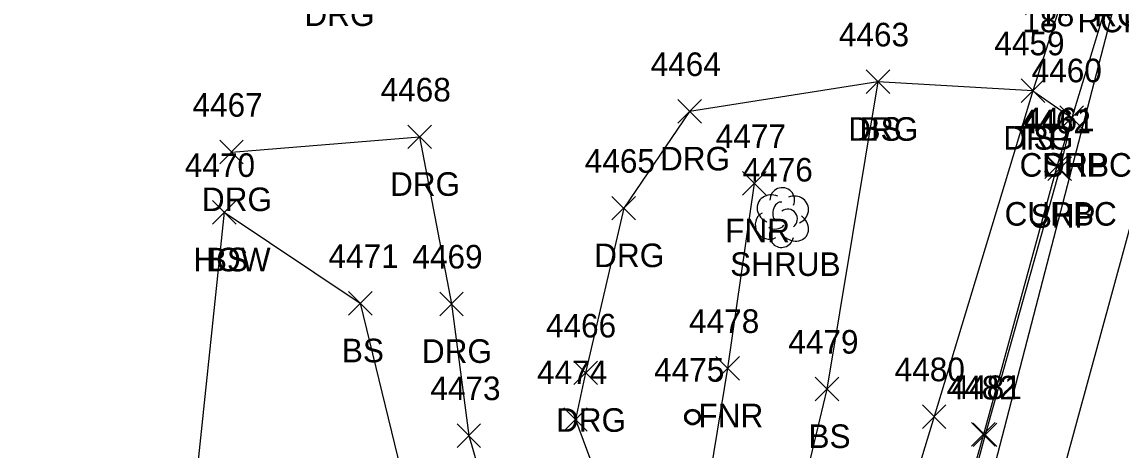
# Model space of a CAD drawing. Extents: x 1443912 to 1445411, y 621446 to 623693.
# Drawn here: x 1444817.3 to 1444910.4, y 623202.8 to 623239.1 of the extents above; entities that cross this region are included whole.
import ezdxf

# ---------------------------------------------------------------- set-up
doc = ezdxf.new("R2010")
doc.units = 0
for name, color, linetype in [('D_C', 7, 'Continuous'), ('DCP', 7, 'Continuous'), ('L_A', 7, 'Continuous'), ('L_I', 7, 'Continuous'), ('L_TIC', 7, 'Continuous'), ('LBC', 7, 'Continuous'), ('LELB', 7, 'Continuous'), ('LFNC', 7, 'Continuous'), ('LSH', 7, 'Continuous'), ('P_A', 7, 'Continuous'), ('P_I', 7, 'Continuous'), ('P_TIC', 7, 'Continuous'), ('PET', 7, 'Continuous'), ('PSP', 7, 'Continuous'), ('R_A', 7, 'Continuous'), ('R_I', 7, 'Continuous'), ('R_TIC', 7, 'Continuous'), ('RC', 7, 'Continuous'), ('RDG', 7, 'Continuous'), ('RDP', 7, 'Continuous'), ('U_I', 7, 'Continuous'), ('UWW', 7, 'Continuous')]:
    doc.layers.add(name, color=color, linetype=linetype)

msp = doc.modelspace()

# ---------------------------------------------------------------- linework, layer by layer
at = {"layer": 'DCP'}
msp.add_lwpolyline([(1444911.563, 623247.238), (1444894.245, 623180.504)], dxfattribs=at)
at = {"layer": 'L_TIC'}
for points in [[(1444888.818, 623233.04), (1444890.818, 623235.04)], [(1444890.818, 623233.04), (1444888.818, 623235.04)], [(1444901.957, 623232.286), (1444903.957, 623234.286)], [(1444903.957, 623232.286), (1444901.957, 623234.286)], [(1444878.337, 623224.428), (1444880.337, 623226.428)], [(1444880.337, 623224.428), (1444878.337, 623226.428)], [(1444833.425, 623221.976), (1444835.425, 623223.976)], [(1444835.425, 623221.976), (1444833.425, 623223.976)], [(1444833.425, 623221.976), (1444835.425, 623223.976)], [(1444835.425, 623221.976), (1444833.425, 623223.976)], [(1444844.947, 623214.264), (1444846.947, 623216.264)], [(1444846.947, 623214.264), (1444844.947, 623216.264)], [(1444876.076, 623208.754), (1444878.076, 623210.754)], [(1444878.076, 623208.754), (1444876.076, 623210.754)], [(1444884.494, 623207), (1444886.494, 623209)], [(1444886.494, 623207), (1444884.494, 623209)], [(1444893.586, 623204.659), (1444895.586, 623206.659)], [(1444895.586, 623204.659), (1444893.586, 623206.659)]]:
    msp.add_lwpolyline(points, dxfattribs=at)
at = {"layer": 'LBC'}
msp.add_lwpolyline([(1444834.425, 623222.976), (1444831.618, 623196.323)], dxfattribs=at)
at = {"layer": 'LELB'}
for points in [[(1444902.957, 623233.286), (1444894.586, 623205.659), (1444889.191, 623187.939), (1444879.578, 623174.577), (1444872.118, 623162.043), (1444873.893, 623154.396), (1444865.845, 623150.18), (1444852.3, 623142.76)], [(1444889.818, 623234.04), (1444885.494, 623208), (1444880.825, 623188.505), (1444872.453, 623183.102), (1444862.516, 623178.532), (1444852.576, 623179.818)], [(1444834.425, 623222.976), (1444845.947, 623215.264), (1444850.417, 623196.823), (1444852.576, 623179.818), (1444839.694, 623178.175), (1444838.752, 623160.519), (1444860.598, 623157.594), (1444858.828, 623151.991), (1444849.747, 623147.245), (1444824.976, 623155.314)]]:
    msp.add_lwpolyline(points, dxfattribs=at)
at = {"layer": 'LFNC'}
msp.add_lwpolyline([(1444879.337, 623225.428), (1444877.076, 623209.754), (1444874.413, 623193.583)], dxfattribs=at)
at = {"layer": 'LSH'}
msp.add_line((1444881.665, 623222.586), (1444881.665, 623222.586), dxfattribs=at)
msp.add_line((1444881.665, 623222.586), (1444881.665, 623222.586), dxfattribs=at)
msp.add_arc((1444881.712, 623224.02), 1.047, 335.52715, 180.95627, dxfattribs=at)
for centre, major_axis, ratio, start_param, end_param in [((1444880.873, 623223.253), (1.21, -0.512), 0.895232, 1.570796, 4.712389), ((1444882.707, 623223.169), (-1.141, -0.483), 0.949671, 1.570796, 4.712389), ((1444881.457, 623223.044), (-0.208, -0.792), 0.645439, 3.141593, 6.283185), ((1444882.165, 623222.419), (-0.5, 0.667), 0.989748, 3.141593, 6.283185), ((1444880.582, 623221.877), (0.584, -1.042), 0.959034, 3.141593, 6.283185), ((1444882.665, 623221.753), (-1.09, 0.792), 0.841452, 1.570796, 4.712389), ((1444881.665, 623221.086), (0.265, 1.061), 0.942809, 1.570796, 4.712389), ((1444881.207, 623221.836), (-0.625, -0.083), 0.423636, 0, 3.141593)]:
    msp.add_ellipse(centre, major_axis=major_axis, ratio=ratio, start_param=start_param, end_param=end_param, dxfattribs=at)
at = {"layer": 'P_TIC'}
for points in [[(1444905.243, 623229.997), (1444907.243, 623231.997)], [(1444907.243, 623229.997), (1444905.243, 623231.997)], [(1444904.229, 623225.669), (1444906.229, 623227.669)], [(1444906.229, 623225.669), (1444904.229, 623227.669)], [(1444897.903, 623203.12), (1444899.903, 623205.12)], [(1444899.903, 623203.12), (1444897.903, 623205.12)]]:
    msp.add_lwpolyline(points, dxfattribs=at)
at = {"layer": 'PET'}
msp.add_lwpolyline([(1445036.702, 623677.704), (1445026.384, 623639.781), (1445008.648, 623576.155), (1444996.948, 623532.888), (1444979.777, 623472.466), (1444964.829, 623416.219), (1444955.709, 623382.545), (1444949.165, 623358.134), (1444939.286, 623323.432), (1444926.274, 623275.909), (1444914.827, 623235.039), (1444901.528, 623186.461), (1444892.14, 623152.692), (1444883.143, 623119.129), (1444870.129, 623073.226), (1444861.494, 623043.31), (1444850.844, 623006.823), (1444834.615, 622954.828), (1444817.277, 622898.327)], dxfattribs=at)
at = {"layer": 'PSP'}
msp.add_lwpolyline([(1444938.45, 623347.365), (1444929.025, 623313.433), (1444928.238, 623309.81), (1444922.874, 623290.92), (1444911.871, 623250.743), (1444910.828, 623246.919), (1444910.341, 623244.449), (1444906.243, 623230.997), (1444905.229, 623226.669), (1444898.903, 623204.12), (1444894.62, 623188.308), (1444891.502, 623176.899), (1444890.541, 623173.344), (1444886.055, 623157.557), (1444885.108, 623153.679), (1444881.771, 623141.713), (1444880.574, 623137.991), (1444874.863, 623117.344), (1444874.119, 623114.36), (1444864.329, 623079.142), (1444854.722, 623044.471)], dxfattribs=at)
at = {"layer": 'R_TIC'}
for points in [[(1444888.818, 623233.04), (1444890.818, 623235.04)], [(1444890.818, 623233.04), (1444888.818, 623235.04)], [(1444901.957, 623232.286), (1444903.957, 623234.286)], [(1444903.957, 623232.286), (1444901.957, 623234.286)], [(1444901.957, 623232.286), (1444903.957, 623234.286)], [(1444903.957, 623232.286), (1444901.957, 623234.286)], [(1444872.863, 623230.527), (1444874.863, 623232.527)], [(1444874.863, 623230.527), (1444872.863, 623232.527)], [(1444905.243, 623229.997), (1444907.243, 623231.997)], [(1444907.243, 623229.997), (1444905.243, 623231.997)], [(1444905.243, 623229.997), (1444907.243, 623231.997)], [(1444907.243, 623229.997), (1444905.243, 623231.997)], [(1444849.979, 623228.373), (1444851.979, 623230.373)], [(1444851.979, 623228.373), (1444849.979, 623230.373)], [(1444834.037, 623227.079), (1444836.037, 623229.079)], [(1444836.037, 623227.079), (1444834.037, 623229.079)], [(1444903.972, 623225.847), (1444905.972, 623227.847)], [(1444905.972, 623225.847), (1444903.972, 623227.847)], [(1444867.282, 623222.33), (1444869.282, 623224.33)], [(1444869.282, 623222.33), (1444867.282, 623224.33)], [(1444852.681, 623214.214), (1444854.681, 623216.214)], [(1444854.681, 623214.214), (1444852.681, 623216.214)], [(1444864.047, 623208.372), (1444866.047, 623210.372)], [(1444866.047, 623208.372), (1444864.047, 623210.372)], [(1444863.189, 623204.416), (1444865.189, 623206.416)], [(1444865.189, 623204.416), (1444863.189, 623206.416)], [(1444854.147, 623203.057), (1444856.147, 623205.057)], [(1444856.147, 623203.057), (1444854.147, 623205.057)], [(1444897.756, 623203.149), (1444899.756, 623205.149)], [(1444899.756, 623203.149), (1444897.756, 623205.149)]]:
    msp.add_lwpolyline(points, dxfattribs=at)
at = {"layer": 'RC'}
msp.add_lwpolyline([(1444906.243, 623230.997), (1444904.972, 623226.847), (1444898.756, 623204.149), (1444894.271, 623188.271), (1444891.321, 623176.989), (1444890.541, 623173.344)], dxfattribs=at)
at = {"layer": 'RDG'}
for points in [[(1444902.957, 623233.286), (1444889.818, 623234.04), (1444873.863, 623231.527), (1444868.282, 623223.33), (1444865.047, 623209.372), (1444864.189, 623205.416), (1444872.453, 623183.102), (1444879.578, 623174.577), (1444885.885, 623171.627)], [(1444835.037, 623228.079), (1444850.979, 623229.373), (1444853.681, 623215.214), (1444855.147, 623204.057), (1444862.516, 623178.532), (1444867.375, 623173.1)]]:
    msp.add_lwpolyline(points, dxfattribs=at)
at = {"layer": 'RDP'}
msp.add_lwpolyline([(1444910.341, 623244.449), (1444906.44, 623244.251), (1444902.957, 623233.286), (1444906.243, 623230.997)], dxfattribs=at)
at = {"layer": 'UWW'}
for radius in [0.667, 0.625, 0.583, 0.542]:
    msp.add_circle((1444874.112, 623205.622), radius, dxfattribs=at)

# ---------------------------------------------------------------- texts
at = {"layer": 'D_C'}
for p in [(1444903.487, 623238.747), (1444902.06, 623238.238)]:
    msp.add_text('18" RCP GOOD', height=2, dxfattribs=at).set_placement(p)
at = {"layer": 'L_A'}
for s, p in [('BS', (1444888.259, 623229.04)), ('TS', (1444901.367, 623228.286)), ('FNR', (1444876.873, 623220.428)), ('HOW', (1444831.811, 623217.976)), ('BS', (1444832.866, 623217.976)), ('SHRUB', (1444877.295, 623217.586)), ('BS', (1444844.388, 623210.264)), ('FNR', (1444874.611, 623204.754)), ('BS', (1444883.935, 623203))]:
    msp.add_text(s, height=2, dxfattribs=at).set_placement(p)
at = {"layer": 'L_I'}
for s, p in [('4463', (1444886.511, 623237.04)), ('4459', (1444899.69, 623236.286)), ('4477', (1444876.078, 623228.428)), ('4470', (1444831.078, 623225.976)), ('4470', (1444831.078, 623225.976)), ('4476', (1444878.35, 623225.586)), ('4471', (1444843.255, 623218.264)), ('4478', (1444873.816, 623212.754)), ('4479', (1444882.227, 623211)), ('4480', (1444891.24, 623208.659))]:
    msp.add_text(s, height=2, dxfattribs=at).set_placement(p)
at = {"layer": 'P_A'}
for p in [(1444903.779, 623225.997), (1444902.765, 623221.669)]:
    msp.add_text('SHP', height=2, dxfattribs=at).set_placement(p)
at = {"layer": 'P_I'}
for s, p in [('4460', (1444902.85, 623233.997)), ('4462', (1444901.922, 623229.669)), ('4482', (1444895.643, 623207.12))]:
    msp.add_text(s, height=2, dxfattribs=at).set_placement(p)
at = {"layer": 'R_A'}
for s, p in [('DRG', (1444841.214, 623238.768)), ('DRG', (1444887.306, 623229.04)), ('DRG', (1444900.445, 623228.286)), ('DRP', (1444900.445, 623228.286)), ('DRG', (1444871.351, 623226.527)), ('CURBC', (1444901.826, 623225.997)), ('DRP', (1444903.732, 623225.997)), ('DRG', (1444848.467, 623224.373)), ('DRG', (1444832.525, 623223.079)), ('CURBC', (1444900.555, 623221.847)), ('DRG', (1444865.77, 623218.33)), ('DRG', (1444851.169, 623210.214)), ('DRG', (1444862.535, 623204.372))]:
    msp.add_text(s, height=2, dxfattribs=at).set_placement(p)
at = {"layer": 'R_I'}
for s, p in [('4463', (1444886.511, 623237.04)), ('4459', (1444899.69, 623236.286)), ('4459', (1444899.69, 623236.286)), ('4464', (1444870.556, 623234.527)), ('4460', (1444902.85, 623233.997)), ('4460', (1444902.85, 623233.997)), ('4468', (1444847.672, 623232.373)), ('4467', (1444831.73, 623231.079)), ('4461', (1444902.232, 623229.847)), ('4465', (1444864.975, 623226.33)), ('4469', (1444850.366, 623218.214)), ('4466', (1444861.685, 623212.372)), ('4474', (1444860.929, 623208.416)), ('4473', (1444851.887, 623207.057)), ('4481', (1444896.063, 623207.149))]:
    msp.add_text(s, height=2, dxfattribs=at).set_placement(p)
at = {"layer": 'U_I'}
msp.add_text('4475', height=2, dxfattribs=at).set_placement((1444870.852, 623208.622))

doc.saveas('drawing.dxf')
